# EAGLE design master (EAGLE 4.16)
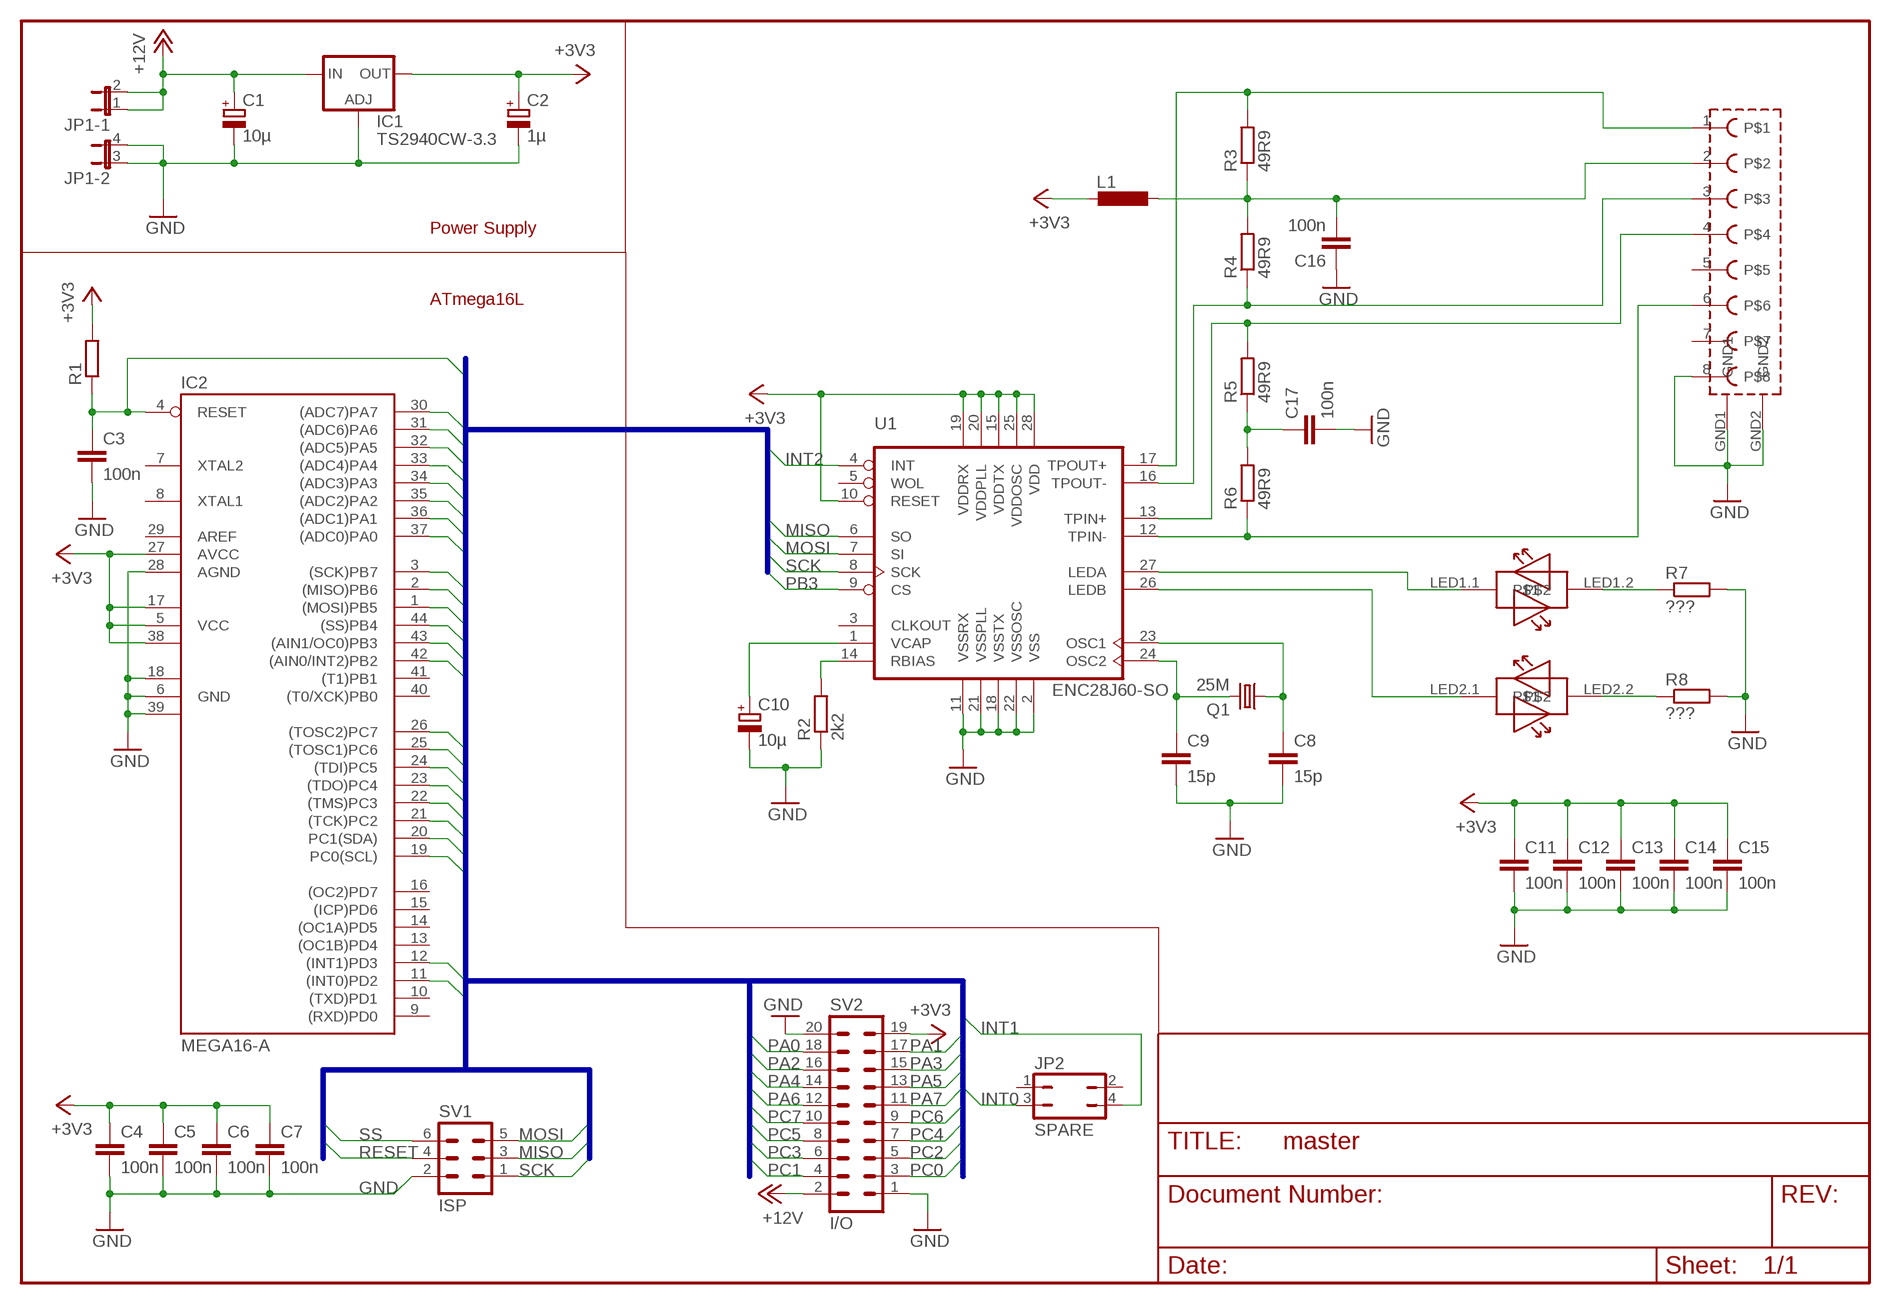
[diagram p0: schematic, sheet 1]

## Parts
C1  10µ  CPOL-EUSMCD  [SMC_D]
C2  1µ  CPOL-EUSMCA  [SMC_A]
C3  100n  C-EUC0805K  [C0805K]
C4  100n  C-EUC0805K  [C0805K]
C5  100n  C-EUC0805K  [C0805K]
C6  100n  C-EUC0805K  [C0805K]
C7  100n  C-EUC0805K  [C0805K]
C8  15p  C-EUC0603  [C0603]
C9  15p  C-EUC0603  [C0603]
C10  10µ  CPOL-EUSMCA  [SMC_A]
C11  100n  C-EUC0805K  [C0805K]
C12  100n  C-EUC0805K  [C0805K]
C13  100n  C-EUC0805K  [C0805K]
C14  100n  C-EUC0805K  [C0805K]
C15  100n  C-EUC0805K  [C0805K]
C16  100n  C-EUC0805K  [C0805K]
C17  100n  C-EUC0805K  [C0805K]
IC1  TS2940CW-3.3  LM317MBSTT3  [SOT223]
IC2  MEGA16-A  [TQFP44]
JP1  JP2QE  [JP2Q]
JP2  SPARE  JP2Q  [JP2Q]
L1  L-EUL2012C  [L2012C]
Q1  25M  CRYTALHC49UP  [HC49UP]
R1  R-EU_R0805  [R0805]
R2  2k2  R-EU_R0805  [R0805]
R3  49R9  R-EU_R0805  [R0805]
R4  49R9  R-EU_R0805  [R0805]
R5  49R9  R-EU_R0805  [R0805]
R6  49R9  R-EU_R0805  [R0805]
R7  ???  R-EU_R0805  [R0805]
R8  ???  R-EU_R0805  [R0805]
SV1  ISP  MA03-2  [MA03-2]
SV2  I/O  MA10-2  [MA10-2]
U1  ENC28J60-SO  [SO28W]
U$1  MAGJACK  [MAGJACK]

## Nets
+3V3: C2.+ C4.1 C5.1 C6.1 C7.1 C11.1 C12.1 C13.1 C14.1 C15.1 IC1.4(OUT) IC2.5(VCC) IC2.17(VCC1) IC2.27(AVCC) IC2.38(VCC2) L1.2 R1.2 SV2.19 U1.10(RESET) U1.15(VDDTX) U1.19(VDDRX) U1.20(VDDPLL) U1.25(VDDOSC) U1.28(VDD)
+12V: C1.+ IC1.3(IN) JP1.1 JP1.2 SV2.2
GND: C1.- C2.- C3.2 C4.2 C5.2 C6.2 C7.2 C8.2 C9.2 C10.- C11.2 C12.2 C13.2 C14.2 C15.2 C16.1 C17.2 IC1.1(ADJ) IC2.6(GND) IC2.18(GND1) IC2.28(AGND) IC2.39(GND2) JP1.3 JP1.4 R2.1 R7.2 R8.2 SV1.2 SV2.1 SV2.20 U1.2(VSS) U1.11(VSSRX) U1.18(VSSTX) U1.21(VSSPLL) U1.22(VSSOSC) U$1.8 U$1.GND1 U$1.GND2
INT0: IC2.11((INT0)PD2) JP2.3
INT1: IC2.12((INT1)PD3) JP2.4
INT2: IC2.42((AIN0/INT2)PB2) U1.4(INT)
MISO: IC2.2((MISO)PB6) SV1.3 U1.6(SO)
MOSI: IC2.1((MOSI)PB5) SV1.5 U1.7(SI)
N$1: R6.1 U1.12(TPIN-) U$1.6
N$2: R2.2 U1.14(RBIAS)
N$3: C10.+ U1.1(VCAP)
N$4: R5.2 U1.13(TPIN+) U$1.4
N$5: C9.1 Q1.2 U1.24(OSC2)
N$6: C8.1 Q1.1 U1.23(OSC1)
N$7: C17.1 R5.1 R6.2
N$8: R4.1 U1.16(TPOUT-) U$1.3
N$9: R3.2 U1.17(TPOUT+) U$1.1
N$10: C16.2 L1.1 R3.1 R4.2 U$1.2
N$11: R7.1 U$1.LED1.2
N$12: R8.1 U$1.LED2.2
N$13: U1.27(LEDA) U$1.LED1.1
N$14: U1.26(LEDB) U$1.LED2.1
PA0: IC2.37((ADC0)PA0) SV2.18
PA1: IC2.36((ADC1)PA1) SV2.17
PA2: IC2.35((ADC2)PA2) SV2.16
PA3: IC2.34((ADC3)PA3) SV2.15
PA4: IC2.33((ADC4)PA4) SV2.14
PA5: IC2.32((ADC5)PA5) SV2.13
PA6: IC2.31((ADC6)PA6) SV2.12
PA7: IC2.30((ADC7)PA7) SV2.11
PB3: IC2.43((AIN1/OC0)PB3) U1.9(CS)
PC0: IC2.19(PC0(SCL)) SV2.3
PC1: IC2.20(PC1(SDA)) SV2.4
PC2: IC2.21((TCK)PC2) SV2.5
PC3: IC2.22((TMS)PC3) SV2.6
PC4: IC2.23((TDO)PC4) SV2.7
PC5: IC2.24((TDI)PC5) SV2.8
PC6: IC2.25((TOSC1)PC6) SV2.9
PC7: IC2.26((TOSC2)PC7) SV2.10
RESET: C3.1 IC2.4(RESET) R1.1 SV1.4
SCK: IC2.3((SCK)PB7) SV1.1 U1.8(SCK)
SS: IC2.44((SS)PB4) SV1.6
Unconnected: IC2.7(XTAL2) IC2.8(XTAL1) IC2.9((RXD)PD0) IC2.10((TXD)PD1) IC2.13((OC1B)PD4) IC2.14((OC1A)PD5) IC2.15((ICP)PD6) IC2.16((OC2)PD7) IC2.40((T0/XCK)PB0) IC2.41((T1)PB1) JP2.1 JP2.2 U1.3(CLKOUT) U1.5(WOL) U$1.5 U$1.7

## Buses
MISO,MOSI,SS,SCK,RESET,PB3,INT0,INT1,INT2,PA[0..7],PC[0..7]

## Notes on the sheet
- Power Supply
- ATmega16L

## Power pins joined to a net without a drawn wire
AREF: IC2.29(AREF)

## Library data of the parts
C1 C2 C10 = rcl:CPOL-EU: POLARIZED CAPACITOR, European symbol
C3-C9 C11-C17 = rcl:C-EU: CAPACITOR, European symbol
IC1 = v-reg:LM317?*: 500 mA Adjustable Output Positive Voltage Regulator Source: http://www.onsemi.co.jp .. LM317M-D.PDF
IC2 = atmel:MEGA16: MICROCONTROLLER 16 Kbytes FLASH 1 kbytes SRAM 512 bytes EEPROM USART 8-channel 10 bit ADC Source: avr.lbr
JP1 = jumper:JP2QE: JUMPER
JP2 = jumper:JP2Q: JUMPER
L1 = rcl:L-EU: INDUCTOR, European symbol
Q1 = crystal:CRYTAL: CRYSTAL
R1-R8 = rcl:R-EU_: RESISTOR, European symbol
SV1 = con-lstb:MA03-2: PIN HEADER
SV2 = con-lstb:MA10-2: PIN HEADER
U1 = microchip-enc28j60:ENC28J60-*: Microchip 10Mbit Eth. contoller with SPI interface
U$1 = magjack:MAGJACK

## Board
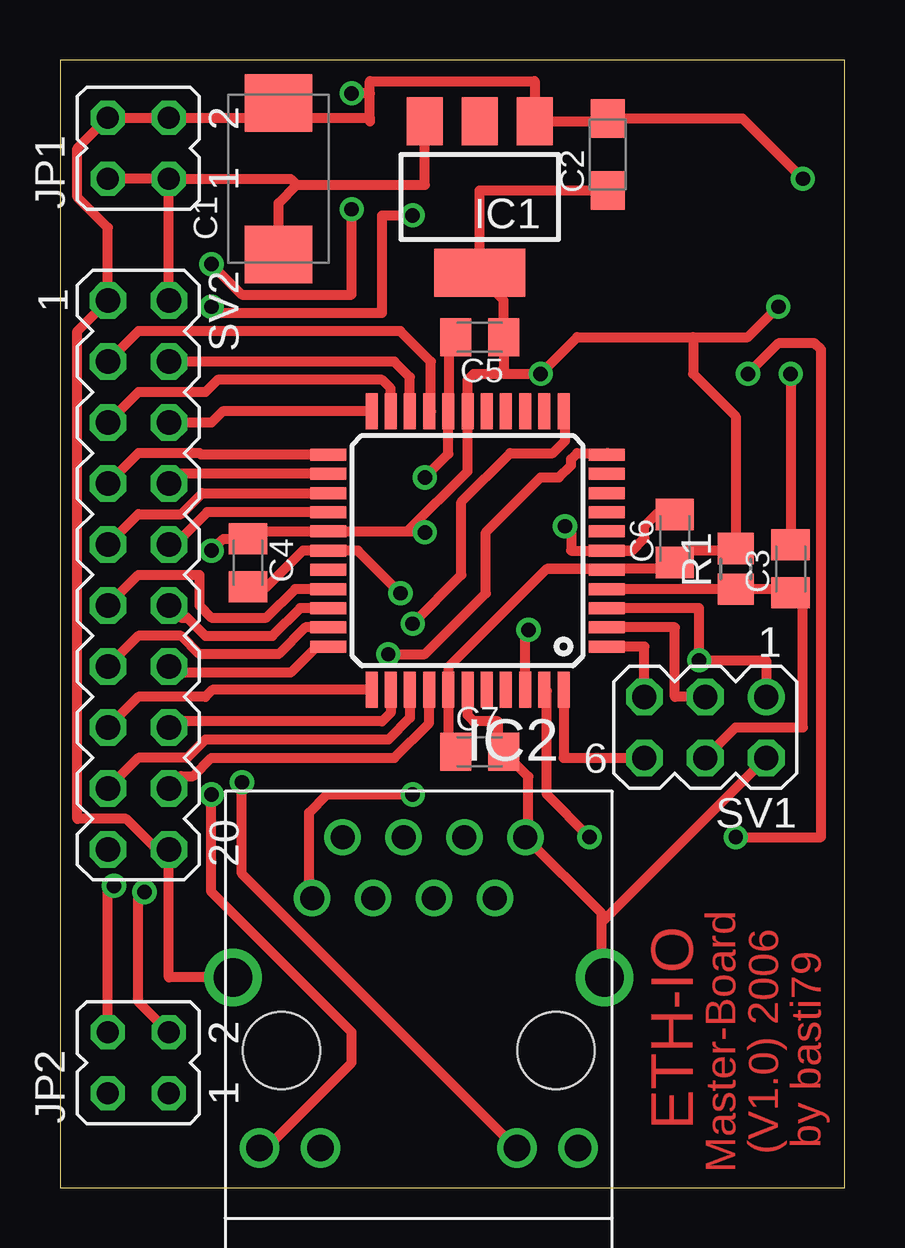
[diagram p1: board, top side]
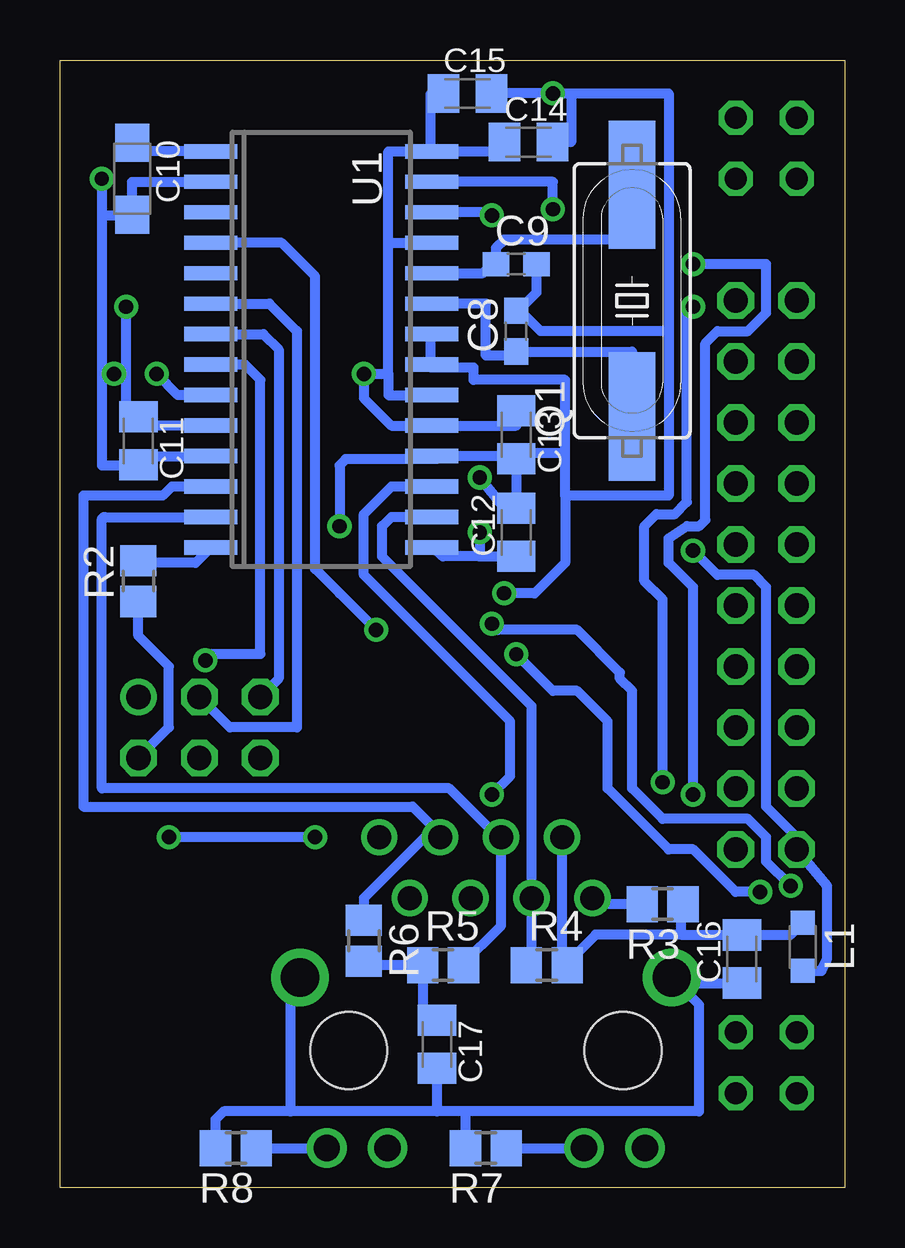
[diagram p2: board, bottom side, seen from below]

Size 32.69 x 46.98 mm. Coordinates in mm from the lower left corner, seen from the top.
Outline: 0,0 32.69,0 32.69,46.98 0,46.98 0,0
Copper layers (1*16): Top 0.035mm / dielectric 1.5mm / Bottom 0.035mm
Design rules "default": minimum track width 10mil, minimum drill 20mil, track to track 8mil, track to pad 8mil, pad to pad 8mil, via to via 8mil, smd to smd 8mil, copper to edge 20mil, drill to drill 8mil, minimum pad ring 10mil, minimum via ring 8mil, stop-mask expansion 4mil, vias tented up to drill 0mil, thermal gap 10mil

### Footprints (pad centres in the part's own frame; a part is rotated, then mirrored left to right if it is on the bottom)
SMC_D = smd 2.4 x 2.8: + -3.15,0; - 3.15,0
SMC_A = smd 1.6 x 1.4: + -1.5,0; - 1.5,0
C0805K = smd 1.3 x 1.6: 1 -1,0; 2 1,0
C0603 = smd 1.1 x 1: 1 -0.85,0; 2 0.85,0
SOT223 = smd 1.5 x 2: 1 -2.3,-3.15; 2 0,-3.15; 3 2.3,-3.15 | smd 3.8 x 2: 4 0,3.15
TQFP44 = smd 1.5 x 0.5: 1 -5.8,4; 2 -5.8,3.2; 3 -5.8,2.4; 4 -5.8,1.6; 5 -5.8,0.8; 6 -5.8,0; 7 -5.8,-0.8; 8 -5.8,-1.6; 9 -5.8,-2.4; 10 -5.8,-3.2; 11 -5.8,-4; 23 5.8,-4; 24 5.8,-3.2; 25 5.8,-2.4; 26 5.8,-1.6; 27 5.8,-0.8; 28 5.8,0; 29 5.8,0.8; 30 5.8,1.6; 31 5.8,2.4; 32 5.8,3.2; 33 5.8,4 | smd 0.5 x 1.5: 12 -4,-5.8; 13 -3.2,-5.8; 14 -2.4,-5.8; 15 -1.6,-5.8; 16 -0.8,-5.8; 17 0,-5.8; 18 0.8,-5.8; 19 1.6,-5.8; 20 2.4,-5.8; 21 3.2,-5.8; 22 4,-5.8; 34 4,5.8; 35 3.2,5.8; 36 2.4,5.8; 37 1.6,5.8; 38 0.8,5.8; 39 0,5.8; 40 -0.8,5.8; 41 -1.6,5.8; 42 -2.4,5.8; 43 -3.2,5.8; 44 -4,5.8
JP2Q = drill 0.914 octagon: 1 -1.27,-1.27; 2 -1.27,1.27; 3 1.27,-1.27; 4 1.27,1.27
L2012C = smd 1 x 1: 1 -1,0; 2 1,0
HC49UP = smd 5.334 x 1.93: 1 -4.826,0; 2 4.826,0
R0805 = smd 1.3 x 1.5: 1 -0.85,0; 2 0.85,0
MA03-2 = drill 1.016 round: 1 -2.54,-1.27 | drill 1.016 octagon: 2 -2.54,1.27; 3 0,-1.27; 4 0,1.27; 5 2.54,-1.27; 6 2.54,1.27
MA10-2 = drill 1.016 octagon: 1 -11.43,-1.27; 2 -11.43,1.27; 3 -8.89,-1.27; 4 -8.89,1.27; 5 -6.35,-1.27; 6 -6.35,1.27; 7 -3.81,-1.27; 8 -3.81,1.27; 9 -1.27,-1.27; 10 -1.27,1.27; 11 1.27,-1.27; 12 1.27,1.27; 13 3.81,-1.27; 14 3.81,1.27; 15 6.35,-1.27; 16 6.35,1.27; 17 8.89,-1.27; 18 8.89,1.27; 19 11.43,-1.27; 20 11.43,1.27
SO28W = smd 0.6 x 2.2: 1 -8.255,-4.6; 2 -6.985,-4.6; 3 -5.715,-4.6; 4 -4.445,-4.6; 5 -3.175,-4.6; 6 -1.905,-4.6; 7 -0.635,-4.6; 8 0.635,-4.6; 9 1.905,-4.6; 10 3.175,-4.6; 11 4.445,-4.6; 12 5.715,-4.6; 13 6.985,-4.6; 14 8.255,-4.6; 15 8.255,4.6; 16 6.985,4.6; 17 5.715,4.6; 18 4.445,4.6; 19 3.175,4.6; 20 1.905,4.6; 21 0.635,4.6; 22 -0.635,4.6; 23 -1.905,4.6; 24 -3.175,4.6; 25 -4.445,4.6; 26 -5.715,4.6; 27 -6.985,4.6; 28 -8.255,4.6
MAGJACK = drill 1 round: 1 -4.445,6.35; 2 -3.175,8.89; 3 -1.905,6.35; 4 -0.635,8.89; 5 0.635,6.35; 6 1.905,8.89; 7 3.175,6.35; 8 4.445,8.89 | drill 1.6 round: GND1 -7.747,3.048; GND2 7.747,3.048 | drill 1.1 round: LED1.1 -6.629,-4.064; LED1.2 -4.089,-4.064; LED2.1 4.089,-4.064; LED2.2 6.629,-4.064 | hole 3.2: -5.715,0; 5.715,0

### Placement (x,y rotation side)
C1  9.11,42.03 90 top
C2  22.82,43.05 90 top
C3  30.44,25.78 90 top
C4  7.84,26.03 270 top
C5  17.49,35.43 180 top
C6  25.62,27.05 90 top
C7  17.49,18.16 0 top
C8  13.68,35.68 90 bottom
C9  13.68,38.48 0 bottom
C10  29.68,42.03 270 bottom
C11  29.43,31.11 270 bottom
C12  13.68,27.3 90 bottom
C13  13.68,31.36 270 bottom
C14  13.17,43.56 0 bottom
C15  15.71,45.59 0 bottom
C16  4.28,9.52 90 bottom
C17  16.98,5.96 270 bottom
IC1  17.49,41.27 180 top
IC2  16.98,26.54 180 top
JP1  3.26,43.3 90 top
JP2  3.26,5.2 90 top
L1  1.74,10.03 270 bottom
Q1  8.85,36.95 90 bottom
R1  28.16,25.78 90 top
R2  29.43,25.27 90 bottom
R3  7.58,11.81 180 bottom
R4  12.41,9.27 0 bottom
R5  16.73,9.27 0 bottom
R6  20.03,10.28 270 bottom
R7  14.95,1.65 180 bottom
R8  25.36,1.65 180 bottom
SV1  26.89,19.17 180 top
SV2  3.26,25.52 270 top
U1  21.81,34.92 270 bottom
U$1  14.95,5.71 0 top

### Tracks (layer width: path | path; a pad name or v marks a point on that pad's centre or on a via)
+3V3  (via drill 0.6)
  Top 0.406: C2.+ 17.49,41.55 IC1.4 17.49,37.97 18.49,36.97 C5.1 18.5,35.43 18.5,34.16 18.38,34.03 | 22.82,25.78 22.78,25.78 IC2.5 22.82,25.78 | 22.82,25.78 25.11,25.78 C6.1 25.62,26.03 26.12,26.54 | 28.16,26.54 R1.2 | 18.38,34.03 18.25,33.9 17.23,33.9 16.98,33.65 IC2.17 16.98,29.84 14.48,27.34 | 18.38,34.03 18.5,34.03 18.5,33.9 v20.03,33.9 21.55,35.43 26.38,35.43 | 14.48,27.34 IC2.27 7.87,27.34 7.58,27.05 C4.1 6.8,27.03 v6.31,26.54 | 14.48,27.34 15.16,27.34 v15.2,27.3 | C7.1 16.22,18.16 16.18,18.19 IC2.38 16.18,21.67 20.28,25.78 | 20.28,25.78 22.82,25.78 | 20.28,25.78 25.87,25.78 25.87,26.28 26.12,26.54 | 28.16,26.54 26.12,26.54 | 28.16,26.54 28.16,32.13 26.38,33.9 26.38,35.43 | 26.38,35.43 28.66,35.43 v29.93,36.7
  Bottom 0.406: C11.1 29.43,32.13 29.04,31.75 | U1.10 29.04,31.75 | 13.68,32.38 C13.1 13.68,31.75 U1.19 18.88,31.75 20.03,32.89 v20.03,33.9 19.01,33.9 | U1.28 19.01,43.17 19.01,39.37 | 19.01,39.37 U1.25 | 19.01,33.9 19.01,39.37 | U1.28 17.23,43.17 17.23,45.59 C15.1 | L1.2 0.96,9.03 0.72,9.52 0.72,12.57 SV2.19 1.99,14.6 3.26,15.87 3.26,25.01 3.77,25.52 5.3,25.52 v6.31,26.54 | U1.20 19.01,33.02 19.01,33.9 | 29.04,31.75 29.93,31.75 v29.93,36.7 | C14.1 14.19,43.56 14.57,43.17 U1.28 | U1.15 17.11,26.66 16.74,26.3 15.2,26.3 | 15.2,26.3 C12.1 | 15.2,26.3 15.2,26.28 | v15.2,27.3 15.2,26.3
+12V
  Top 0.406: JP1.1 JP1.2 | IC1.3 15.2,44.42 15.2,41.78 9.87,41.78 | JP1.1 9.61,42.03 9.87,41.78 | SV2.2 JP1.1 | C1.+ 9.11,41.02 9.87,41.78
GND  (via drill 0.6)
  Top 0.406: 12.92,44.57 12.92,45.59 | 12.92,44.57 12.92,44.42 | 12.92,45.59 12.92,46.1 19.77,46.1 19.77,44.42 IC1.1 22.57,44.42 22.57,44.55 | 22.57,44.55 22.57,44.57 | 22.57,44.55 C2.- 28.43,44.55 v30.95,42.03 | 29.17,17.9 SV1.2 22.57,11.04 | 7.58,25.01 C4.2 7.33,25.01 8.6,25.01 10.12,26.54 IC2.28 12.41,26.54 v14.19,24.76 | IC2.39 16.98,19.68 17.23,19.43 18.25,19.43 18.25,18.66 18.5,18.41 C7.2 19.52,17.12 19.52,14.6 U$1.8 22.57,11.43 22.57,11.04 | 23.84,26.54 IC2.6 | 24.35,27.55 24.85,28.06 25.62,28.06 C6.2 | U$1.GND2 22.57,8.76 22.57,11.04 | 12.92,45.59 v12.15,45.59 | 7.33,8.76 U$1.GND1 4.53,8.76 SV2.20 4.03,14.09 2.76,15.36 0.72,15.36 0.72,35.68 SV2.1 1.99,40 0.72,41.27 0.72,43.3 JP1.4 JP1.3 8.6,44.57 | 24.35,27.55 24.84,28.05 | 24.35,27.55 24.35,27.05 23.84,26.54 | 23.84,26.54 21.3,26.54 21.3,27.3 v21.04,27.55 | 16.22,35.16 C5.2 16.47,35.43 16.22,35.17 16.22,32.34 IC2.18 16.18,30.56 v15.2,29.59 | C1.- 9.11,45.08 8.6,44.57 | 8.6,44.57 12.92,44.57 | v30.44,33.9 C3.2
  Bottom 0.406: 13.68,30.48 C13.2 13.68,30.35 | 13.68,30.48 U1.18 17.11,30.48 16.98,30.35 20.79,30.35 21.04,30.09 v21.04,27.55 | 13.68,30.6 13.68,30.48 | 13.68,30.35 13.68,28.32 | 17.23,34.28 17.23,34.16 15.46,34.16 15.46,33.65 11.65,33.65 11.65,30.6 | 17.23,34.28 U1.21 | U1.22 17.23,35.55 17.23,34.28 | U1.2 29.68,41.91 C10.- 29.68,40.51 30.95,40.51 | 11.65,30.6 13.68,30.6 | 13.68,30.6 13.68,30.35 | 11.65,28.82 11.65,30.6 | C15.2 v12.15,45.59 11.39,45.59 | 30.95,40.51 30.95,33.9 | 30.95,33.9 30.95,30.09 29.68,30.09 29.68,30.11 C11.2 29.43,30.09 29.04,30.48 U1.11 | 15.71,3.17 6.06,3.17 6.06,7.62 U$1.GND1 7.07,8.76 6.84,8.52 C16.1 | 15.71,3.17 16.98,3.17 | 16.98,3.17 23.08,3.17 | U$1.GND2 22.57,8.76 23.08,8.25 23.08,3.17 | 16.98,3.17 C17.2 | v30.95,42.03 30.95,40.51 | 11.65,28.82 11.65,26.03 12.92,24.76 v14.19,24.76 | 13.68,28.32 C12.2 | v15.2,29.59 14.19,28.32 13.68,28.32 | R2.1 29.43,22.98 28.16,21.71 28.16,19.17 SV1.2 | R7.2 15.8,3.08 15.71,3.17 | R8.2 26.21,2.83 25.87,3.17 23.08,3.17 | C14.2 11.39,43.56 11.39,45.59 | 13.68,36.44 C8.2 | C9.2 12.83,37.29 13.68,36.44 | 13.68,36.44 13.42,36.44 12.66,35.68 7.33,35.68 | 11.65,28.82 7.33,28.82 7.33,35.68 | 7.33,35.68 7.33,45.59 11.39,45.59 | 30.95,33.9 v30.44,33.9
INT0  (via drill 0.6)
  Top 0.406: JP2.3 3.26,7.74 3.26,12.06 v3.52,12.31 | v13.68,22.22 15.2,22.22 17.74,24.76 17.74,27.3 20.03,29.59 20.79,29.59 21.3,30.09 21.3,30.35 21.55,30.6 22.82,30.6 22.78,30.56 IC2.11
  Bottom 0.406: v3.52,12.31 4.53,12.31 6.31,14.09 7.33,14.09 9.87,16.63 9.87,19.43 11.14,20.7 12.15,20.7 v13.68,22.22
INT1  (via drill 0.6)
  Top 0.406: JP2.4 1.99,12.31 v2.25,12.57 | IC2.12 20.98,32.19 21.04,32.13 21.04,31.11 20.54,30.6 18.76,30.6 16.73,28.57 16.73,25.52 v14.69,23.49
  Bottom 0.406: v2.25,12.57 3.26,13.58 3.26,14.6 4.03,15.36 7.58,15.36 8.85,16.63 8.85,20.7 9.36,21.2 9.36,21.46 11.14,23.24 14.44,23.24 v14.69,23.49
INT2  (via drill 0.6)
  Top 0.406: IC2.42 19.38,23.1 arc-90 v19.52,23.24
  Bottom 0.406: U1.4 23.46,39.37 22.06,37.97 22.06,25.78 21.04,24.76 v19.52,23.24
MISO
  Top 0.406: IC2.2 25.62,23.34 25.62,20.44 SV1.3
  Bottom 0.406: U1.6 23.96,36.83 22.82,35.68 22.82,19.17 25.62,19.17 SV1.3
MOSI
  Top 0.406: IC2.1 24.35,22.54 SV1.5
  Bottom 0.406: U1.7 24.22,35.55 23.58,34.92 23.58,21.2 SV1.5
N$1
  Bottom 0.406: 20.03,11.04 R6.1 20.03,12.06 17.49,14.6 U$1.6 16.73,14.6 18,15.87 31.71,15.87 31.71,28.82 28.41,28.82 28.03,29.2 U1.12
N$2
  Bottom 0.406: R2.2 29.43,26.03 27.04,26.03 U1.14
N$3
  Bottom 0.406: 29.68,43.56 C10.+ 29.68,43.17 U1.1
N$4
  Bottom 0.406: R5.2 15.96,9.27 14.31,10.92 U$1.4 14.44,14.6 16.47,16.63 30.95,16.63 30.95,27.81 arc90 30.82,27.93 U1.13
N$5
  Bottom 0.406: Q1.2 9.11,41.52 9.11,39.75 9.36,39.49 14.19,39.49 14.53,39.15 C9.1 14.69,38.48 15.08,38.09 U1.24
N$6
  Bottom 0.406: U1.23 14.95,36.83 14.95,34.67 13.68,34.67 C8.1 | C8.1 13.68,34.92 | 8.85,31.87 Q1.1 8.85,34.83 C8.1
N$7
  Bottom 0.406: R6.2 20.03,9.52 19.77,9.27 R5.1 17.58,7.32 17.22,6.96 C17.1
N$8
  Bottom 0.406: R4.1 13.04,9.27 U$1.3 13.04,20.06 14.95,21.97 | U1.16 18.88,27.93 19.27,27.55 19.27,26.28 14.95,21.97 | 14.95,21.97 14.69,21.71
N$9  (via drill 0.6)
  Top 0.406: v14.69,16.38 11.14,16.38 10.38,15.62 10.38,12.31 10.63,12.06 U$1.1
  Bottom 0.406: U1.17 18.88,29.2 20.03,28.06 20.03,25.52 13.93,19.43 13.93,17.14 v14.69,16.38 | U$1.1 10.63,12.06 10.38,11.81 R3.2
N$10
  Bottom 0.406: 11.39,9.27 R4.2 11.65,9.27 | U$1.2 11.77,9.27 11.65,9.27 | 11.65,9.27 11.9,9.27 | R3.1 6.82,11.81 6.82,10.54 | 6.82,10.54 10.38,10.54 11.65,9.27 | L1.1 1.74,11.04 2.26,10.52 C16.2 4.28,10.54 6.82,10.54
N$11
  Bottom 0.406: R7.1 U$1.LED1.2
N$12
  Bottom 0.406: 21.55,1.65 U$1.LED2.2 R8.1
N$13  (via drill 0.6)
  Top 0.406: v12.15,40.76 12.15,37.21 7.58,37.21 v6.31,38.48 | v6.31,16.38 6.31,12.31 12.15,6.47 12.15,5.2 8.6,1.65 U$1.LED1.1
  Bottom 0.406: U1.27 12.15,41.91 v12.15,40.76 | v6.31,38.48 3.26,38.48 3.26,36.44 4.03,35.68 5.3,35.68 5.8,35.17 5.8,27.81 6.06,27.55 6.57,27.55 7.33,27.05 7.33,26.03 6.31,25.01 v6.31,16.38
N$14  (via drill 0.6)
  Top 0.406: v14.69,40.51 13.42,40.51 13.42,36.44 6.31,36.44 v6.31,36.7 | U$1.LED2.1 19.01,1.65 7.58,13.08 v7.58,16.89
  Bottom 0.406: U1.26 14.69,40.63 v14.69,40.51 | v7.58,16.89 7.58,24.51 8.34,25.27 8.34,27.55 7.84,28.06 7.07,28.06 6.57,28.57 6.57,36.7 v6.31,36.7
PA0
  Top 0.406: IC2.37 15.38,19.35 13.93,17.9 6.31,17.9 5.55,17.14 5.04,17.14 SV2.18
PA1
  Top 0.406: IC2.36 14.58,19.57 13.68,18.66 6.06,18.66 5.3,17.9 3.26,17.9 SV2.17
PA2
  Top 0.406: IC2.35 13.78,19.78 13.42,19.43 4.79,19.43 SV2.16
PA3
  Top 0.406: IC2.34 6.35,20.74 6.06,20.44 3.26,20.44 SV2.15
PA4
  Top 0.406: IC2.33 10.69,22.54 9.61,21.46 4.79,21.46 SV2.14
PA5
  Top 0.406: IC2.32 10.22,23.34 9.11,22.22 5.8,22.22 5.04,22.98 3.26,22.98 SV2.13
PA6
  Top 0.406: SV2.12 5.04,23.74 5.3,23.74 6.06,22.98 8.85,22.98 10.01,24.14 IC2.31
PA7
  Top 0.406: SV2.11 3.26,25.52 5.8,25.52 5.8,24.25 6.31,23.74 8.6,23.74 9.79,24.94 IC2.30
PB3  (via drill 0.6)
  Top 0.406: v28.16,14.6 31.71,14.6 31.71,34.92 31.46,35.17 29.93,35.17 v28.66,33.9 | IC2.43 20.22,20.7 20.28,20.7 20.28,16.38 v22.06,14.6
  Bottom 0.406: U1.9 27.77,33.02 v28.66,33.9 | v22.06,14.6 v28.16,14.6
PC0
  Top 0.406: IC2.19 15.46,32.34 15.46,34.41 14.19,35.68 3.26,35.68 SV2.3
PC1
  Top 0.406: IC2.20 14.58,33.76 13.93,34.41 SV2.4
PC2
  Top 0.406: IC2.21 13.78,33.29 13.42,33.65 6.57,33.65 6.06,33.14 3.26,33.14 SV2.5
PC3
  Top 0.406: IC2.22 6.78,32.34 6.31,31.87 SV2.6
PC4
  Top 0.406: IC2.23 5.87,30.54 5.8,30.6 3.26,30.6 SV2.7
PC5
  Top 0.406: IC2.24 4.94,29.74 SV2.8
PC6
  Top 0.406: IC2.25 5.92,28.94 5.04,28.06 3.26,28.06 SV2.9
PC7
  Top 0.406: SV2.10 4.79,26.79 6.13,28.14 IC2.26
RESET
  Top 0.406: IC2.4 27.98,24.94 arc-90 28.16,24.76 R1.1 30.28,24.93 arc-90 30.44,24.76 | SV1.4 28.16,19.17 30.95,19.17 30.95,24.76 30.44,24.76 | 30.44,24.76 C3.1
SCK  (via drill 0.6)
  Top 0.406: IC2.3 26.63,24.14 v26.63,21.97 29.43,21.97 SV1.1
  Bottom 0.406: U1.8 24.98,34.28 24.35,33.65 24.35,22.22 26.38,22.22 v26.63,21.97
SS
  Top 0.406: IC2.44 20.98,17.9 SV1.6

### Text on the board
Top: ETH-IO | by basti79 | Master-Board | (V1.0) 2006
